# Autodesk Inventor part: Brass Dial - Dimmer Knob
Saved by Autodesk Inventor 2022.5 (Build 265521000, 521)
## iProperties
Created: 2025-02
Part Number: Brass Dial - Dimmer Knob
Material: Generic
Document SubType Name: Modeling
Designer: AdminForWorker
Density: 1 g/cm^3
Appearance: Default
Title: Brass Dial - Dimmer Knob
Author: AdminForWorker
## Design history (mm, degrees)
feature "Brass Dial - Dimmer Knob"
body "Solid1"
